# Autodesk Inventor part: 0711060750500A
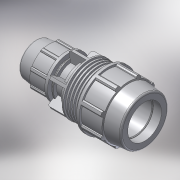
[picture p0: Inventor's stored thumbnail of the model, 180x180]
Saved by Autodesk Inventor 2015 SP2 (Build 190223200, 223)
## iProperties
Created: 2017-02
Part Number: 0711060750500A
Material: PVC-Piping
Description: PLASSON REDUCING COUPLER 75-50
Document SubType Name: Modeling
Designer: KIM
Mass: 92.6774 g
Surface Area: 199.44 cm^2
Volume: 66.1981 cm^3
Density: 1.4 g/cm^3
Appearance: Smooth - White
Author: KIM
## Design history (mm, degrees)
derived "87110.ipt"
feature "Solid1::87110.ipt"
tag "TaggingFeature1"
body "Solid1"
other parameters: "d2" = 75, "d4" = 20.41667, "d5" = 35, "d7" = 134, "d9" = 35, "d11" = 3.5, "d12" = 107.2, "d13" = 120 deg, "d14" = 105, "d15" = 6 deg, "d16" = 120.6, "d18" = 3.75, "d19" = 35 deg, "d20" = 17.5 deg, "d21" = 124.62, "d23" = 0, "d25" = 360 deg, "d27" = 2.68, "d42" = 53.9, "d46" = 1.5, "d51" = 245, "d52" = 35, "d53" = 8 deg, "d54" = 132, "d58" = 67.5, "d59" = 45, "d60" = 86.4, "d61" = 76.8, "d62" = 30.625, "d63" = 44.1, "d64" = 120 deg, "d65" = 96, "d68" = 17.5, "d74" = 89.28, "d75" = 35 deg, "d76" = 17.5 deg, "d78" = 0, "d80" = 360 deg, "d85" = 1.92, "d88" = 1, "d93" = 98, "d94" = 93.8, "d98" = 6.4, "d99" = 0, "d100" = 5.36, "d102" = 360 deg, "d104" = 2, "d106" = 0, "d107" = 6.4, "d108" = 0, "d109" = 6.4, "d110" = 0, "d111" = 3.55, "d112" = 3.55, "d113" = 3.55, "d114" = 2.96, "d116" = 2.96, "d119" = 5.92, "d125" = 118.188, "d_" = 75, "E_" = 134, "H_" = 245, "l_" = 132, "E_1" = 96, "l_1" = 98, "d96" = 10.65, "d115" = 29.6
